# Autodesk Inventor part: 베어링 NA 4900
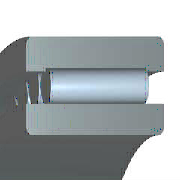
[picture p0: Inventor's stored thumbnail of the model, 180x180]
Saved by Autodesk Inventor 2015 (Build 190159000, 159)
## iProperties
Created: 2014-07
Part Number: 베어링 NA 4900
Material: Steel, Mild
Description: 니들 롤러 베어링 - 경계 치수 및 공차
Document SubType Name: Modeling
Standard: KS B 2029
Designer: KYOUNG IL JANG
Standards Organization: KS
Language: ko-KR
Size Designation: NA 4900 - 10 x 22 x 13
Categories: <MemberInstance><Categories><Category DisplayName="샤프트 부품" InternalName="7f7aeb1f-a693-4053-b835-cee3144e0d98" Mnemonic="SHFT"><Category DisplayName="베어링" Inter
Density: 7.85 g/cm^3
Appearance: Steel
Mass: 23.791 g
Surface Area: 38.613 cm^2
Volume: 3.0307 cm^3
Company: 한국ATC센터
IsCustomPart: 0
Author: KYOUNG IL JANG
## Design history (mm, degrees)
revolve "본체" stored, may be unused: angle "d17" = 90 deg
revolve "롤러" stored, may be unused: angle "d18" = 90 deg
pattern_circular "IDS_ARRAYROLLER[SIMPL:T]" dims angle "d2" = 360 deg
body "Solid1"
sketch "스케치"
  geometry: L1 (1.857, 9)-(11.143, 9); L2 (11.143, 9)-(11.143, 7); L3 (13, 7)-(0, 7); L4 (1.857, 7)-(1.857, 9); L5 (1.857, 8)-(11.143, 8); L6 (6.5, 8)-(6.5, 7); L7 (0, 5)-(13, 5); L8 (0, 11)-(13, 11); L9 (13, 5)-(13, 7); L10 (13, 8.8)-(13, 11); L11 (1.857, 8.8)-(0, 8.8); L12 (11.143, 8.8)-(13, 8.8); L13 (-6, 0)-(36, 0) reference; L14 (0, -1.9)-(0, 14.9) reference
  constraints: 24 end point, 8 point on line, 3 midpoint, 3 parallel, 3 perpendicular, 2 symmetric about line, 1 horizontal, 1 other
  dimensions: "d6" = 10 diameter of L7 L13 (= WD); "d7" = 14 diameter of L3 L13 (= KID1); "d8" = 22 diameter of L8 L13 (= BD); "d9" = 16 diameter of L6.start L13 (= 0.5 x WD + 0.5 x BD); "d10" = 17.6 diameter of L12 L13 (= 0.9 x BD + 0.9 x WD - 0.8 x KID1); "d11" = 18 diameter of L1 L13 (= BD + WD - KID1); "d12" = 1.85714 distance between parallel lines of L14 L4 (= 0.142857 x KB); "d13" = 13 distance between parallel lines of L14 L9 (= KB); "d14" = 11.14286 distance between parallel lines of L14 L2 (= 0.857143 x KB)
fillet "모깎기1" dims "d0" = 0.3 (= KRS)
other parameters: "WD" = 10 [user parameter; used in 6 equation terms], "BD" = 22 [user parameter; used in 6 equation terms], "KB" = 13 [user parameter; used in 3 equation terms], "KID1" = 14 [user parameter; used in 4 equation terms], "KRS" = 0.3 [user parameter; used in 1 equation term], "d3" = 0, "d4" = 0, "d5" = 0, "d15" = 0, "d16" = 0, "BC0" = 9150000 [user parameter], "WR" = 5 (= 0.5 x WD) [user parameter], "BBA" = 0 [user parameter], "BC" = 8150000 [user parameter], "BR" = 11 (= 0.5 x BD) [user parameter]
